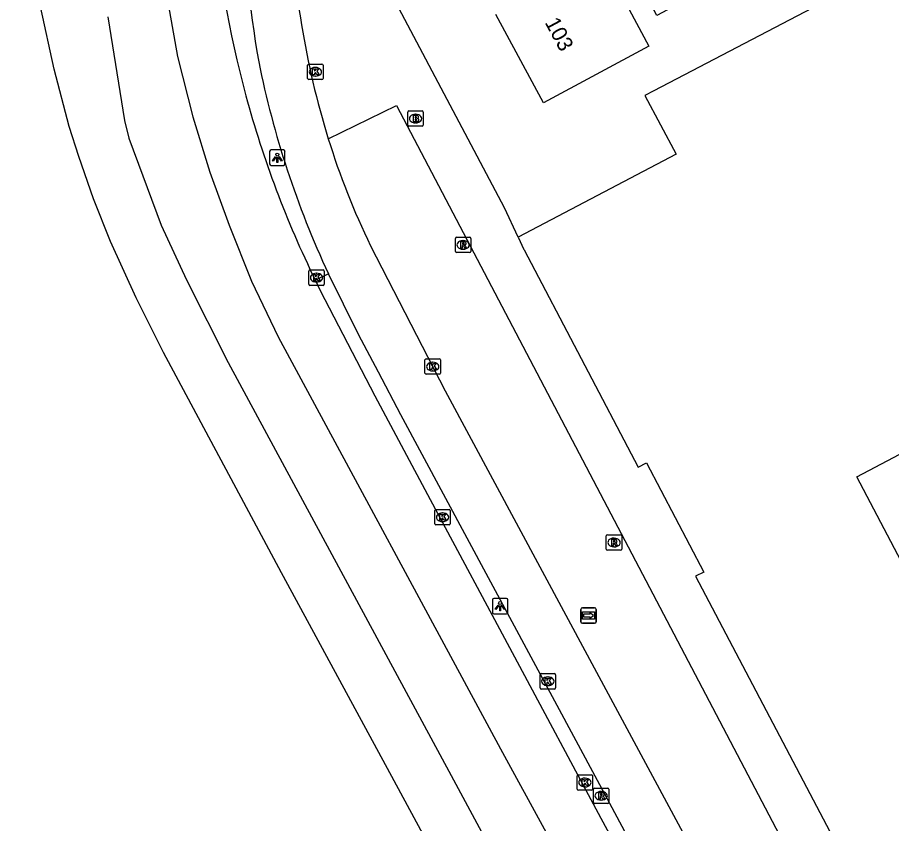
# Model space of a CAD drawing. Extents: x 162880 to 165536, y 384011 to 385179.
# Drawn here: x 162910.2 to 162966.8, y 384118.4 to 384170.7 of the extents above; entities that cross this region are included whole.
import ezdxf

# ---------------------------------------------------------------- set-up
doc = ezdxf.new("R2010")
doc.units = 0
for name, color, linetype in [('IMGEO_Berm_open', 7, 'Continuous'), ('IMGEO_Brandkraan', 7, 'Continuous'), ('IMGEO_Fietspad_open', 7, 'Continuous'), ('IMGEO_Groenvoorziening', 7, 'Continuous'), ('IMGEO_Kolk', 7, 'Continuous'), ('IMGEO_Lichtpunt', 7, 'Continuous'), ('IMGEO_Muur', 7, 'Continuous'), ('IMGEO_Pand', 7, 'Continuous'), ('IMGEO_Pand_nummerreeks', 7, 'Continuous'), ('IMGEO_Rijbaan_lokaal_open', 7, 'Continuous'), ('IMGEO_Rijbaan_regionaal_gesloten', 7, 'Continuous'), ('IMGEO_Rioolput', 7, 'Continuous'), ('IMGEO_Voetpad_open', 7, 'Continuous'), ('IMGEO_Wegwijzer', 7, 'Continuous')]:
    doc.layers.add(name, color=color, linetype=linetype)

msp = doc.modelspace()

# ---------------------------------------------------------------- linework, layer by layer
at = {"layer": 'IMGEO_Berm_open'}
msp.add_lwpolyline([(162930.309, 384154.083), (162929.465, 384153.664)], dxfattribs=at)
at = {"layer": 'IMGEO_Brandkraan'}
for p, q in [((162935.453, 384163.718), (162935.453, 384164.57)), ((162935.528, 384164.644), (162936.38, 384164.644)), ((162935.941, 384164.424), (162935.966, 384164.424)), ((162936.454, 384164.57), (162936.454, 384163.718)), ((162935.964, 384163.864), (162935.939, 384163.864)), ((162936.38, 384163.644), (162935.528, 384163.644))]:
    msp.add_line(p, q, dxfattribs=at)
for points in [[(162935.453, 384163.718), (162935.453, 384164.57)], [(162935.528, 384164.644), (162936.38, 384164.644)], [(162936.454, 384164.57), (162936.454, 384163.718)], [(162935.801, 384164.344), (162935.801, 384163.944), (162936.014, 384163.944)], [(162936.032, 384164.344), (162935.801, 384164.344)], [(162935.98, 384164.263), (162935.926, 384164.263), (162935.926, 384164.187)], [(162935.926, 384164.187), (162935.979, 384164.187)], [(162935.988, 384164.111), (162935.926, 384164.111), (162935.926, 384164.03)], [(162935.926, 384164.03), (162935.988, 384164.03)], [(162936.38, 384163.644), (162935.528, 384163.644)]]:
    msp.add_lwpolyline(points, dxfattribs=at)
for centre, radius, start, end in [((162935.53, 384164.568), 0.0765, 91.552, 178.448), ((162935.53, 384164.568), 0.0765, 91.552, 178.448), ((162936.378, 384164.568), 0.0765, 1.552, 88.448), ((162936.378, 384164.568), 0.0765, 1.552, 88.448), ((162935.981, 384164.225), 0.0379, 267.8285, 90.9355), ((162935.989, 384164.07), 0.0404, 269.8759, 90.5077), ((162936.02, 384164.195), 0.251, 268.6676, 293.5347), ((162936.036, 384164.199), 0.145, 59.4692, 91.5367), ((162936.061, 384164.246), 0.0922, 285.5137, 58.1501), ((162936.066, 384164.054), 0.105, 301.3115, 78.989), ((162935.53, 384163.72), 0.0765, 181.552, 268.448), ((162935.53, 384163.72), 0.0765, 181.552, 268.448), ((162936.378, 384163.72), 0.0765, 271.552, 358.448), ((162936.378, 384163.72), 0.0765, 271.552, 358.448)]:
    msp.add_arc(centre, radius, start, end, dxfattribs=at)
for centre, major_axis, ratio, start_param, end_param in [((162935.94, 384164.144), (-0.387, 0.002), 0.722429, 4.712389, 7.853982), ((162935.965, 384164.144), (-0.39, 0.002), 0.717154, 1.570796, 4.712389)]:
    msp.add_ellipse(centre, major_axis=major_axis, ratio=ratio, start_param=start_param, end_param=end_param, dxfattribs=at)
at = {"layer": 'IMGEO_Fietspad_open'}
for points in [[(162933.038, 384155.899), (162937.872, 384146.488), (162947.223, 384129.106), (162953.721, 384117.028)], [(162978.275, 384064.218), (162977.652, 384065.394), (162972.657, 384074.738), (162967.836, 384083.704), (162960.872, 384096.737), (162947.738, 384121.235), (162934.999, 384144.935), (162933.549, 384147.714), (162932.265, 384150.139), (162930.309, 384154.083)]]:
    msp.add_lwpolyline(points, dxfattribs=at)
for centre, radius, start, end in [((163010.743, 384182.395), 86.191, 175.2495, 189.73487), ((162984.182, 384179.392), 56.368, 181.6649, 197.079), ((162985.777, 384179.928), 61.193, 191.41095, 204.98284), ((162978.098, 384177.69), 50.052, 197.2631, 205.8091)]:
    msp.add_arc(centre, radius, start, end, dxfattribs=at)
at = {"layer": 'IMGEO_Groenvoorziening'}
msp.add_lwpolyline([(162963.675, 384178.458), (162963.724, 384178.168), (162965.607, 384174.74), (162965.09, 384173.113), (162951.391, 384165.934), (162950.819, 384165.634), (162952.828, 384161.829), (162942.595, 384156.45)], dxfattribs=at)
at = {"layer": 'IMGEO_Kolk'}
for p, q in [((162928.965, 384166.749), (162928.965, 384167.601)), ((162929.04, 384167.675), (162929.892, 384167.675)), ((162929.453, 384167.455), (162929.478, 384167.455)), ((162929.966, 384167.601), (162929.966, 384166.749)), ((162929.476, 384166.895), (162929.451, 384166.895)), ((162929.892, 384166.675), (162929.04, 384166.675)), ((162929.039, 384153.406), (162929.039, 384154.258)), ((162929.114, 384154.332), (162929.966, 384154.332)), ((162930.04, 384154.258), (162930.04, 384153.406)), ((162929.527, 384154.112), (162929.552, 384154.112)), ((162929.966, 384153.332), (162929.114, 384153.332)), ((162929.55, 384153.552), (162929.525, 384153.552)), ((162936.641, 384148.568), (162937.493, 384148.568)), ((162936.566, 384147.642), (162936.566, 384148.494)), ((162937.054, 384148.348), (162937.079, 384148.348)), ((162937.567, 384148.494), (162937.567, 384147.642)), ((162937.493, 384147.568), (162936.641, 384147.568)), ((162937.077, 384147.788), (162937.052, 384147.788)), ((162937.203, 384137.875), (162937.203, 384138.727)), ((162937.278, 384138.801), (162938.13, 384138.801)), ((162937.691, 384138.581), (162937.716, 384138.581)), ((162938.204, 384138.727), (162938.204, 384137.875)), ((162938.13, 384137.801), (162937.278, 384137.801)), ((162937.714, 384138.021), (162937.689, 384138.021)), ((162944.024, 384127.237), (162944.024, 384128.089)), ((162944.099, 384128.163), (162944.951, 384128.163)), ((162944.512, 384127.943), (162944.537, 384127.943)), ((162945.025, 384128.089), (162945.025, 384127.237)), ((162944.951, 384127.163), (162944.099, 384127.163)), ((162944.535, 384127.383), (162944.51, 384127.383)), ((162946.428, 384120.676), (162946.428, 384121.528)), ((162946.503, 384121.602), (162947.355, 384121.602)), ((162946.916, 384121.382), (162946.941, 384121.382)), ((162947.429, 384121.528), (162947.429, 384120.676)), ((162946.939, 384120.822), (162946.914, 384120.822)), ((162947.355, 384120.602), (162946.503, 384120.602))]:
    msp.add_line(p, q, dxfattribs=at)
for points in [[(162928.965, 384166.749), (162928.965, 384167.601)], [(162929.04, 384167.675), (162929.892, 384167.675)], [(162929.286, 384167.375), (162929.409, 384167.375), (162929.409, 384167.224), (162929.539, 384167.375), (162929.703, 384167.375), (162929.557, 384167.224), (162929.71, 384166.975), (162929.558, 384166.975), (162929.473, 384167.139), (162929.409, 384167.072), (162929.409, 384166.975), (162929.286, 384166.975), (162929.286, 384167.375)], [(162929.966, 384167.601), (162929.966, 384166.749)], [(162929.892, 384166.675), (162929.04, 384166.675)], [(162929.039, 384153.406), (162929.039, 384154.258)], [(162929.114, 384154.332), (162929.966, 384154.332)], [(162930.04, 384154.258), (162930.04, 384153.406)], [(162929.36, 384154.032), (162929.483, 384154.032), (162929.483, 384153.881), (162929.613, 384154.032), (162929.777, 384154.032), (162929.631, 384153.881), (162929.784, 384153.632), (162929.632, 384153.632), (162929.547, 384153.796), (162929.483, 384153.729), (162929.483, 384153.632), (162929.36, 384153.632), (162929.36, 384154.032)], [(162929.966, 384153.332), (162929.114, 384153.332)], [(162936.641, 384148.568), (162937.493, 384148.568)], [(162936.566, 384147.642), (162936.566, 384148.494)], [(162936.887, 384148.268), (162937.01, 384148.268), (162937.01, 384148.117), (162937.14, 384148.268), (162937.304, 384148.268), (162937.158, 384148.117), (162937.311, 384147.868), (162937.159, 384147.868), (162937.074, 384148.032), (162937.01, 384147.965), (162937.01, 384147.868), (162936.887, 384147.868), (162936.887, 384148.268)], [(162937.567, 384148.494), (162937.567, 384147.642)], [(162937.493, 384147.568), (162936.641, 384147.568)], [(162937.203, 384137.875), (162937.203, 384138.727)], [(162937.278, 384138.801), (162938.13, 384138.801)], [(162937.524, 384138.501), (162937.647, 384138.501), (162937.647, 384138.35), (162937.777, 384138.501), (162937.941, 384138.501), (162937.795, 384138.35), (162937.948, 384138.101), (162937.796, 384138.101), (162937.711, 384138.265), (162937.647, 384138.198), (162937.647, 384138.101), (162937.524, 384138.101), (162937.524, 384138.501)], [(162938.204, 384138.727), (162938.204, 384137.875)], [(162938.13, 384137.801), (162937.278, 384137.801)], [(162944.024, 384127.237), (162944.024, 384128.089)], [(162944.099, 384128.163), (162944.951, 384128.163)], [(162944.345, 384127.863), (162944.468, 384127.863), (162944.468, 384127.712), (162944.598, 384127.863), (162944.762, 384127.863), (162944.616, 384127.712), (162944.769, 384127.463), (162944.617, 384127.463), (162944.532, 384127.627), (162944.468, 384127.56), (162944.468, 384127.463), (162944.345, 384127.463), (162944.345, 384127.863)], [(162945.025, 384128.089), (162945.025, 384127.237)], [(162944.951, 384127.163), (162944.099, 384127.163)], [(162946.428, 384120.676), (162946.428, 384121.528)], [(162946.503, 384121.602), (162947.355, 384121.602)], [(162947.429, 384121.528), (162947.429, 384120.676)], [(162946.749, 384121.302), (162946.872, 384121.302), (162946.872, 384121.151), (162947.002, 384121.302), (162947.166, 384121.302), (162947.02, 384121.151), (162947.173, 384120.902), (162947.021, 384120.902), (162946.936, 384121.066), (162946.872, 384120.999), (162946.872, 384120.902), (162946.749, 384120.902), (162946.749, 384121.302)], [(162947.355, 384120.602), (162946.503, 384120.602)]]:
    msp.add_lwpolyline(points, dxfattribs=at)
for centre, start, end in [((162929.042, 384167.599), 91.552, 178.448), ((162929.042, 384167.599), 91.552, 178.448), ((162929.89, 384167.599), 1.552, 88.448), ((162929.89, 384167.599), 1.552, 88.448), ((162929.042, 384166.751), 181.552, 268.448), ((162929.042, 384166.751), 181.552, 268.448), ((162929.89, 384166.751), 271.552, 358.448), ((162929.89, 384166.751), 271.552, 358.448), ((162929.116, 384154.256), 91.552, 178.448), ((162929.116, 384154.256), 91.552, 178.448), ((162929.964, 384154.256), 1.552, 88.448), ((162929.964, 384154.256), 1.552, 88.448), ((162929.116, 384153.408), 181.552, 268.448), ((162929.116, 384153.408), 181.552, 268.448), ((162929.964, 384153.408), 271.552, 358.448), ((162929.964, 384153.408), 271.552, 358.448), ((162936.643, 384148.492), 91.552, 178.448), ((162936.643, 384148.492), 91.552, 178.448), ((162937.491, 384148.492), 1.552, 88.448), ((162937.491, 384148.492), 1.552, 88.448), ((162936.643, 384147.644), 181.552, 268.448), ((162936.643, 384147.644), 181.552, 268.448), ((162937.491, 384147.644), 271.552, 358.448), ((162937.491, 384147.644), 271.552, 358.448), ((162937.28, 384138.725), 91.552, 178.448), ((162937.28, 384138.725), 91.552, 178.448), ((162938.128, 384138.725), 1.552, 88.448), ((162938.128, 384138.725), 1.552, 88.448), ((162937.28, 384137.877), 181.552, 268.448), ((162937.28, 384137.877), 181.552, 268.448), ((162938.128, 384137.877), 271.552, 358.448), ((162938.128, 384137.877), 271.552, 358.448), ((162944.101, 384128.087), 91.552, 178.448), ((162944.101, 384128.087), 91.552, 178.448), ((162944.949, 384128.087), 1.552, 88.448), ((162944.949, 384128.087), 1.552, 88.448), ((162944.101, 384127.239), 181.552, 268.448), ((162944.101, 384127.239), 181.552, 268.448), ((162944.949, 384127.239), 271.552, 358.448), ((162944.949, 384127.239), 271.552, 358.448), ((162946.505, 384121.526), 91.552, 178.448), ((162946.505, 384121.526), 91.552, 178.448), ((162947.353, 384121.526), 1.552, 88.448), ((162947.353, 384121.526), 1.552, 88.448), ((162946.505, 384120.678), 181.552, 268.448), ((162946.505, 384120.678), 181.552, 268.448), ((162947.353, 384120.678), 271.552, 358.448), ((162947.353, 384120.678), 271.552, 358.448)]:
    msp.add_arc(centre, 0.0765, start, end, dxfattribs=at)
for centre, major_axis, ratio, start_param, end_param in [((162929.452, 384167.175), (-0.387, 0.002), 0.722429, 4.712389, 7.853982), ((162929.477, 384167.175), (-0.39, 0.002), 0.717154, 1.570796, 4.712389), ((162929.526, 384153.832), (-0.387, 0.002), 0.722429, 4.712389, 7.853982), ((162929.551, 384153.832), (-0.39, 0.002), 0.717154, 1.570796, 4.712389), ((162937.053, 384148.068), (-0.387, 0.002), 0.722429, 4.712389, 7.853982), ((162937.078, 384148.068), (-0.39, 0.002), 0.717154, 1.570796, 4.712389), ((162937.69, 384138.301), (-0.387, 0.002), 0.722429, 4.712389, 7.853982), ((162937.715, 384138.301), (-0.39, 0.002), 0.717154, 1.570796, 4.712389), ((162944.511, 384127.663), (-0.387, 0.002), 0.722429, 4.712389, 7.853982), ((162944.536, 384127.663), (-0.39, 0.002), 0.717154, 1.570796, 4.712389), ((162946.915, 384121.102), (-0.387, 0.002), 0.722429, 4.712389, 7.853982), ((162946.94, 384121.102), (-0.39, 0.002), 0.717154, 1.570796, 4.712389)]:
    msp.add_ellipse(centre, major_axis=major_axis, ratio=ratio, start_param=start_param, end_param=end_param, dxfattribs=at)
at = {"layer": 'IMGEO_Lichtpunt'}
for p, q in [((162926.501, 384162.013), (162926.501, 384161.206)), ((162926.501, 384162.013), (162926.501, 384161.206)), ((162927.403, 384162.108), (162926.595, 384162.108)), ((162927.403, 384162.108), (162926.595, 384162.108)), ((162927.497, 384161.206), (162927.497, 384162.013)), ((162927.497, 384161.206), (162927.497, 384162.013)), ((162926.595, 384161.112), (162927.403, 384161.112)), ((162926.595, 384161.112), (162927.403, 384161.112)), ((162940.935, 384132.939), (162940.935, 384132.132)), ((162940.935, 384132.939), (162940.935, 384132.132)), ((162941.837, 384133.034), (162941.029, 384133.034)), ((162941.837, 384133.034), (162941.029, 384133.034)), ((162941.931, 384132.132), (162941.931, 384132.939)), ((162941.931, 384132.132), (162941.931, 384132.939)), ((162941.029, 384132.038), (162941.837, 384132.038)), ((162941.029, 384132.038), (162941.837, 384132.038))]:
    msp.add_line(p, q, dxfattribs=at)
for points in [[(162926.875, 384161.677), (162926.914, 384161.649), (162926.726, 384161.387), (162926.688, 384161.414), (162926.875, 384161.677)], [(162926.977, 384161.629), (162927.024, 384161.629), (162927.024, 384161.307), (162926.977, 384161.307), (162926.977, 384161.629)], [(162927.087, 384161.649), (162927.125, 384161.676), (162927.312, 384161.414), (162927.273, 384161.386), (162927.087, 384161.649)], [(162941.309, 384132.603), (162941.348, 384132.575), (162941.16, 384132.313), (162941.122, 384132.34), (162941.309, 384132.603)], [(162941.411, 384132.555), (162941.458, 384132.555), (162941.458, 384132.233), (162941.411, 384132.233), (162941.411, 384132.555)], [(162941.521, 384132.575), (162941.559, 384132.602), (162941.746, 384132.34), (162941.707, 384132.312), (162941.521, 384132.575)]]:
    msp.add_lwpolyline(points, dxfattribs=at)
for centre in [(162927, 384161.811), (162941.434, 384132.737)]:
    msp.add_circle(centre, 0.0994, dxfattribs=at)
for centre, start, end in [((162926.595, 384162.013), 90, 180), ((162926.595, 384162.013), 90, 180), ((162927.403, 384162.013), 0, 90), ((162927.403, 384162.013), 0, 90), ((162926.595, 384161.206), 180, 270), ((162926.595, 384161.206), 180, 270), ((162927.403, 384161.206), 270, 0), ((162927.403, 384161.206), 270, 360), ((162941.029, 384132.939), 90, 180), ((162941.029, 384132.939), 90, 180), ((162941.837, 384132.939), 0, 90), ((162941.837, 384132.939), 0, 90), ((162941.029, 384132.132), 180, 270), ((162941.029, 384132.132), 180, 270), ((162941.837, 384132.132), 270, 0), ((162941.837, 384132.132), 270, 360)]:
    msp.add_arc(centre, 0.0946, start, end, dxfattribs=at)
at = {"layer": 'IMGEO_Muur'}
msp.add_lwpolyline([(162951.391, 384165.934), (162950.819, 384165.634), (162952.828, 384161.829), (162942.595, 384156.45)], dxfattribs=at)
at = {"layer": 'IMGEO_Pand'}
msp.add_lwpolyline([(162957.085, 384179.365), (162956.925, 384179.279), (162958.221, 384176.868), (162955.578, 384175.448), (162956.61, 384173.527), (162951.589, 384170.83), (162950.69, 384172.503), (162949.466, 384171.845), (162951.077, 384168.848), (162944.242, 384165.175), (162941.166, 384170.898)], dxfattribs=at)
at = {"layer": 'IMGEO_Rijbaan_lokaal_open'}
msp.add_lwpolyline([(162969.176, 384132.079), (162964.552, 384140.92), (162993.049, 384155.957)], dxfattribs=at)
at = {"layer": 'IMGEO_Rijbaan_regionaal_gesloten'}
for points in [[(162925.808, 384218.268), (162924.406, 384214.339), (162923.042, 384210.566), (162921.831, 384206.759), (162921.005, 384203.8), (162920.142, 384199.922), (162919.5, 384195.956), (162919.067, 384191.957), (162918.781, 384187.947), (162918.728, 384184.033), (162918.834, 384180.023), (162919.29, 384176.002), (162919.842, 384172.079), (162920.544, 384168.175), (162921.527, 384164.257), (162922.622, 384160.668), (162923.876, 384157.224), (162925.32, 384153.606), (162927.054, 384149.995), (162941.468, 384123.295), (162975.292, 384061.236)], [(162989.779, 384019.039), (162985.285, 384027.338), (162969.546, 384056.451), (162934.139, 384122.004), (162927.269, 384134.699), (162919.627, 384148.98), (162917.856, 384152.526), (162916.199, 384156.183), (162915.086, 384158.94), (162914.148, 384161.675), (162913.523, 384163.62), (162912.54, 384167.345), (162911.658, 384171.418), (162910.97, 384175.312), (162910.653, 384178.24), (162910.532, 384181.105), (162910.375, 384184.971), (162910.273, 384188.816), (162910.227, 384197.762), (162910.167, 384200.723)], [(162916.031, 384170.737), (162917.1, 384164.017), (162917.376, 384162.869), (162919.483, 384157.241), (162921.12, 384153.691), (162923.818, 384148.334), (162938.264, 384121.566), (162958.401, 384084.137), (162968.149, 384066.24), (162972.6, 384059.067)], [(162977.549, 384063.861), (162975.924, 384066.775), (162972.201, 384073.655), (162969.056, 384079.527), (162966.347, 384084.631), (162960.687, 384095.222), (162957.998, 384100.168), (162953.892, 384107.862), (162947.989, 384118.779), (162942.396, 384129.219), (162936.921, 384139.438), (162933.346, 384146.147), (162929.808, 384152.971), (162929.465, 384153.664)]]:
    msp.add_lwpolyline(points, dxfattribs=at)
for centre, radius, start, end in [((162997.888, 384185.169), 75.493, 175.66641, 195.00433), ((162988.785, 384182.789), 66.085, 195.05462, 206.14984)]:
    msp.add_arc(centre, radius, start, end, dxfattribs=at)
at = {"layer": 'IMGEO_Rioolput'}
for p, q in [((162938.533, 384155.528), (162938.533, 384156.38)), ((162938.608, 384156.454), (162939.46, 384156.454)), ((162939.021, 384156.234), (162939.046, 384156.234)), ((162939.534, 384156.38), (162939.534, 384155.528)), ((162939.46, 384155.454), (162938.608, 384155.454)), ((162939.044, 384155.674), (162939.019, 384155.674)), ((162948.312, 384136.235), (162948.312, 384137.087)), ((162948.387, 384137.161), (162949.239, 384137.161)), ((162948.8, 384136.941), (162948.825, 384136.941)), ((162949.313, 384137.087), (162949.313, 384136.235)), ((162949.239, 384136.161), (162948.387, 384136.161)), ((162948.823, 384136.381), (162948.798, 384136.381)), ((162947.48, 384119.813), (162947.48, 384120.665)), ((162947.555, 384120.739), (162948.407, 384120.739)), ((162947.968, 384120.519), (162947.993, 384120.519)), ((162948.481, 384120.665), (162948.481, 384119.813)), ((162948.407, 384119.739), (162947.555, 384119.739)), ((162947.991, 384119.959), (162947.966, 384119.959))]:
    msp.add_line(p, q, dxfattribs=at)
for points in [[(162938.533, 384155.528), (162938.533, 384156.38)], [(162938.608, 384156.454), (162939.46, 384156.454)], [(162939.122, 384156.152), (162938.87, 384156.154), (162938.87, 384155.754)], [(162939.048, 384156.073), (162938.994, 384156.073), (162938.994, 384155.992)], [(162938.994, 384155.992), (162939.046, 384155.992)], [(162939.534, 384156.38), (162939.534, 384155.528)], [(162939.46, 384155.454), (162938.608, 384155.454)], [(162938.87, 384155.754), (162938.994, 384155.754), (162938.994, 384155.916), (162939.005, 384155.916)], [(162939.052, 384155.887), (162939.123, 384155.754), (162939.263, 384155.754), (162939.198, 384155.88)], [(162948.312, 384136.235), (162948.312, 384137.087)], [(162948.387, 384137.161), (162949.239, 384137.161)], [(162948.901, 384136.859), (162948.649, 384136.861), (162948.649, 384136.461)], [(162948.827, 384136.78), (162948.773, 384136.78), (162948.773, 384136.699)], [(162948.773, 384136.699), (162948.825, 384136.699)], [(162949.313, 384137.087), (162949.313, 384136.235)], [(162949.239, 384136.161), (162948.387, 384136.161)], [(162948.649, 384136.461), (162948.773, 384136.461), (162948.773, 384136.623), (162948.784, 384136.623)], [(162948.831, 384136.594), (162948.902, 384136.461), (162949.042, 384136.461), (162948.977, 384136.587)], [(162947.48, 384119.813), (162947.48, 384120.665)], [(162947.555, 384120.739), (162948.407, 384120.739)], [(162948.069, 384120.437), (162947.817, 384120.439), (162947.817, 384120.039)], [(162947.995, 384120.358), (162947.941, 384120.358), (162947.941, 384120.277)], [(162947.941, 384120.277), (162947.993, 384120.277)], [(162948.481, 384120.665), (162948.481, 384119.813)], [(162948.407, 384119.739), (162947.555, 384119.739)], [(162947.817, 384120.039), (162947.941, 384120.039), (162947.941, 384120.201), (162947.952, 384120.201)], [(162947.999, 384120.172), (162948.07, 384120.039), (162948.21, 384120.039), (162948.145, 384120.165)]]:
    msp.add_lwpolyline(points, dxfattribs=at)
for centre, radius, start, end in [((162938.61, 384156.378), 0.0765, 91.552, 178.448), ((162938.61, 384156.378), 0.0765, 91.552, 178.448), ((162939.03, 384156.181), 0.19, 274.7715, 282.9687), ((162939.054, 384155.977), 0.0964, 77.0061, 93.1865), ((162939.068, 384156.034), 0.0378, 276.6634, 79.6772), ((162939.121, 384156.042), 0.109, 350.3612, 89.416), ((162939.119, 384156.042), 0.112, 277.5842, 350.9817), ((162939.103, 384155.827), 0.108, 29.5134, 73.7905), ((162939.458, 384156.378), 0.0765, 1.552, 88.448), ((162939.458, 384156.378), 0.0765, 1.552, 88.448), ((162938.61, 384155.53), 0.0765, 181.552, 268.448), ((162938.61, 384155.53), 0.0765, 181.552, 268.448), ((162939.004, 384155.863), 0.0533, 26.0293, 88.6989), ((162939.458, 384155.53), 0.0765, 271.552, 358.448), ((162939.458, 384155.53), 0.0765, 271.552, 358.448), ((162948.389, 384137.085), 0.0765, 91.552, 178.448), ((162948.389, 384137.085), 0.0765, 91.552, 178.448), ((162948.809, 384136.888), 0.19, 274.7715, 282.9687), ((162948.833, 384136.684), 0.0964, 77.0061, 93.1865), ((162948.847, 384136.741), 0.0378, 276.6634, 79.6772), ((162948.9, 384136.749), 0.109, 350.3612, 89.416), ((162948.898, 384136.749), 0.112, 277.5842, 350.9817), ((162949.237, 384137.085), 0.0765, 1.552, 88.448), ((162949.237, 384137.085), 0.0765, 1.552, 88.448), ((162948.389, 384136.237), 0.0765, 181.552, 268.448), ((162948.389, 384136.237), 0.0765, 181.552, 268.448), ((162948.783, 384136.57), 0.0533, 26.0293, 88.6989), ((162948.882, 384136.534), 0.108, 29.5134, 73.7905), ((162949.237, 384136.237), 0.0765, 271.552, 358.448), ((162949.237, 384136.237), 0.0765, 271.552, 358.448), ((162947.557, 384120.663), 0.0765, 91.552, 178.448), ((162947.557, 384120.663), 0.0765, 91.552, 178.448), ((162947.977, 384120.466), 0.19, 274.7715, 282.9687), ((162948.001, 384120.262), 0.0964, 77.0061, 93.1865), ((162948.015, 384120.319), 0.0378, 276.6634, 79.6772), ((162948.068, 384120.327), 0.109, 350.3612, 89.416), ((162948.066, 384120.327), 0.112, 277.5842, 350.9817), ((162948.405, 384120.663), 0.0765, 1.552, 88.448), ((162948.405, 384120.663), 0.0765, 1.552, 88.448), ((162947.557, 384119.815), 0.0765, 181.552, 268.448), ((162947.557, 384119.815), 0.0765, 181.552, 268.448), ((162947.951, 384120.148), 0.0533, 26.0293, 88.6989), ((162948.05, 384120.112), 0.108, 29.5134, 73.7905), ((162948.405, 384119.815), 0.0765, 271.552, 358.448), ((162948.405, 384119.815), 0.0765, 271.552, 358.448)]:
    msp.add_arc(centre, radius, start, end, dxfattribs=at)
for centre, major_axis, ratio, start_param, end_param in [((162939.02, 384155.954), (-0.387, 0.002), 0.722429, 4.712389, 7.853982), ((162939.045, 384155.954), (-0.39, 0.002), 0.717154, 1.570796, 4.712389), ((162948.799, 384136.661), (-0.387, 0.002), 0.722429, 4.712389, 7.853982), ((162948.824, 384136.661), (-0.39, 0.002), 0.717154, 1.570796, 4.712389), ((162947.967, 384120.239), (-0.387, 0.002), 0.722429, 4.712389, 7.853982), ((162947.992, 384120.239), (-0.39, 0.002), 0.717154, 1.570796, 4.712389)]:
    msp.add_ellipse(centre, major_axis=major_axis, ratio=ratio, start_param=start_param, end_param=end_param, dxfattribs=at)
at = {"layer": 'IMGEO_Voetpad_open'}
for points in [[(162942.595, 384156.45), (162941.707, 384158.354), (162931.731, 384177.249)], [(162930.3, 384162.837), (162934.711, 384164.997), (162962.245, 384112.496), (162962.739, 384111.555), (162972.528, 384092.889), (162984.67, 384069.309)], [(162942.595, 384156.45), (162942.963, 384155.663), (162942.983, 384155.624), (162950.386, 384141.542), (162950.906, 384141.816), (162954.621, 384134.748), (162954.097, 384134.472), (162962.154, 384119.148), (162970.391, 384103.478)]]:
    msp.add_lwpolyline(points, dxfattribs=at)
at = {"layer": 'IMGEO_Wegwijzer'}
for p, q in [((162946.664, 384131.525), (162946.664, 384132.325)), ((162946.664, 384132.325), (162946.664, 384131.525)), ((162946.764, 384132.425), (162947.554, 384132.425)), ((162947.554, 384132.425), (162946.764, 384132.425)), ((162947.654, 384132.325), (162947.654, 384131.525)), ((162947.654, 384131.525), (162947.654, 384132.325)), ((162947.554, 384131.425), (162946.764, 384131.425)), ((162946.764, 384131.425), (162947.554, 384131.425))]:
    msp.add_line(p, q, dxfattribs=at)
for points in [[(162946.765, 384132.157), (162947.553, 384132.157), (162947.553, 384131.693), (162946.765, 384131.693), (162946.765, 384132.157)], [(162946.83, 384132.009), (162946.83, 384131.925), (162946.83, 384131.841), (162947.241, 384131.841), (162947.241, 384131.758), (162947.488, 384131.925), (162947.241, 384132.092), (162947.241, 384132.009), (162946.83, 384132.009)]]:
    msp.add_lwpolyline(points, dxfattribs=at)
for centre, start, end in [((162946.764, 384132.325), 90, 180), ((162946.764, 384132.325), 90, 180), ((162947.554, 384132.325), 0, 90), ((162947.554, 384132.325), 360, 90), ((162946.764, 384131.525), 180, 270), ((162946.764, 384131.525), 180, 270), ((162947.554, 384131.525), 270, 0), ((162947.554, 384131.525), 270, 0)]:
    msp.add_arc(centre, 0.1, start, end, dxfattribs=at)

# ---------------------------------------------------------------- texts
at = {"layer": 'IMGEO_Pand_nummerreeks'}
msp.add_text('103', height=1, rotation=298.2562, dxfattribs=at).set_placement((162944.306, 384170.378))

doc.saveas('drawing.dxf')
